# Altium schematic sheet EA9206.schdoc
size 127 x 101 mm
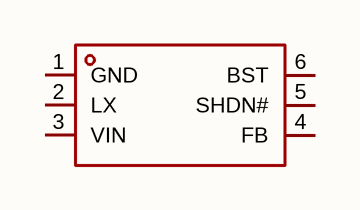
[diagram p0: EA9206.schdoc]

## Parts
U?  ea9206  [TSOT-23-6_L2.9-W1.6-P0.95-LS2.8-BL]  (value not drawn)

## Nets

Not connected (* = marked no-connect by the designer): U? 1(GND) 2(LX) 3(VIN) 4(FB) 5(SHDN#) 6(BST)

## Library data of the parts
U? = ea9206: 功能类型:降压型;工作电压:4.5V~20V;输出电压:768mV~8V;输出电流:3A;输出类型:可调;; Manufacturer: everanalog(申风); AddInBom: yes; ModelId: 2c4039b5b88644c1bda4b4ba9e971667; ModelName: TSOT-23-6_L2.9-W1.6-H1.1-LS2.8-P0.95; ModelTransform: 110.236,114.173,0,90,0,0,0,0,0; Function: 降压型; Output Current: 3A; Synchronous Rectifier: 是; Number of Outputs: 1; Topology: 降压式; Quiescent Current: 300uA; Switch tube (built-in/external): 内置; Output Type: 可调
